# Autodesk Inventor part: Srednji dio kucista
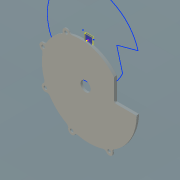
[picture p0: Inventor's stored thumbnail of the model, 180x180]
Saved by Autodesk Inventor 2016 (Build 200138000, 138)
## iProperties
Created: 2015-04
Part Number: Srednji dio kucista
Material: Generic
Document SubType Name: Modeling
Designer: Uglješa
Density: 1 g/cm^3
Appearance: Default
Mass: 541.1 g
Surface Area: 1236.25 cm^2
Volume: 541.1 cm^3
Author: Uglješa
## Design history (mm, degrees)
sketch "Sketch1"
  geometry: L1 (76.246, -47.553)-(76.198, -109.059) reference; L2 (136.981, -109.107)-(76.198, -109.059) reference; A1 r 119.037 centre (-15.855, -122.966) between (76.246, -47.553) and (0.079, -5) reference; A2 r 127.464 centre (9.536, -106.9) between (-0.099, -234) and (136.981, -109.107) reference; A3 r 127.292 centre (10.292, -107.133) between (-117, -106.909) and (-0.099, -234) reference; 2 further points
  constraints: 6 point on circle, 4 end point, 3 centre point, 25 other
workplane "Work Plane1"
sketch "Sketch3"
  geometry: 1 further point
workplane "Work Plane2"
extrude "Extrusion3" new body sketch "Sketch1" distance "d6" = 4; taper "d7" = 0 deg; dims "d104" = 4, "d105" = 0
workplane "Work Plane3"
sketch "Sketch9"
  geometry: C1 r 14 at (0, -107); C2 r 2.65 at (0, -107) reference; 1 further point
  constraints: 1 centre point, 1 concentric
  dimensions: "d31" = 28 diameter of C1
extrude "Extrusion7" cut sketch "Sketch9" stored distance "d32" = 80; taper "d33" = 0 deg
sketch "Sketch17"
  geometry: 1 further point
sketch "Sketch18"
  geometry: L1 (78.245, -48.794)-(78.204, -102.061) reference; L2 (83.2, -107.065)-(134.9, -107.105) reference; C1 r 4.5 at (-110.388, -165.646) reference; C2 r 4.5 at (-38.051, -231.307) reference; C3 r 4.5 at (64.746, -228.869) reference; C4 r 14 at (0, -107); A1 r 5 centre (73.245, -48.79) between (78.245, -48.794) and (77.152, -45.669) reference; A2 r 5 centre (83.204, -102.065) between (78.204, -102.061) and (83.2, -107.065) reference; A3 r 10 centre (64.746, -228.869) between (55.915, -233.561) and (73.577, -224.177) reference; A4 r 130.357 centre (9.643, -107.008) between (-0.101, -237) and (46.96, -231.909) reference; A5 r 130.417 centre (10.417, -107.008) between (-21.515, -233.455) and (-0.101, -237) reference; A6 r 10 centre (-38.051, -231.307) between (-47.613, -228.38) and (-28.489, -234.234) reference; A7 r 130.417 centre (10.417, -107.008) between (-98.388, -178.91) and (-52.658, -221.157) reference; A8 r 10 centre (-110.388, -165.646) between (-115.08, -156.815) and (-105.697, -174.477) reference; A9 r 130.417 centre (10.417, -107.008) between (-120, -106.907) and (-113.516, -147.62) reference; A10 r 10 centre (-116.657, -71.291) between (-113.73, -61.729) and (-119.584, -80.853) reference; A11 r 10 centre (-53.485, -6.326) between (-44.654, -1.634) and (-62.316, -11.017) reference; A12 r 4.5 centre (-116.657, -71.291) between (-115.23, -75.559) and (-112.889, -68.831) reference; A13 r 4.5 centre (-116.657, -71.291) between (-112.889, -68.831) and (-115.23, -75.559) reference; A14 r 4.5 centre (-53.485, -6.326) between (-56.289, -9.846) and (-49.073, -7.207) reference; A15 r 4.5 centre (-53.485, -6.326) between (-49.073, -7.207) and (-56.289, -9.846) reference; A16 r 119.037 centre (-15.853, -119.966) between (67.678, -35.157) and (0.082, -2) reference; A17 r 130.357 centre (9.643, -107.008) between (78.06, -217.968) and (139.892, -112.308) reference; 4 further points
  constraints: 34 point on circle, 21 centre point, 4 end point, 118 other
  dimensions: "d101" = 28 diameter of C4
sketch "Sketch19"
  geometry: C1 r 14 at (0, -107) reference; C2 r 67.5 at (0, -107); 1 further point
  constraints: 1 centre point, 1 coincident
  dimensions: "d95" = 135 diameter of C2
extrude "Extrusion15" cut sketch "Sketch19" distance "d96" = 5; taper "d97" = 0 deg
extrude "Extrusion16" join sketch "Sketch18" distance "d102" = 3; taper "d103" = 0 deg
fillet "Fillet6" dims "d106" = 2
body "Solid1"
